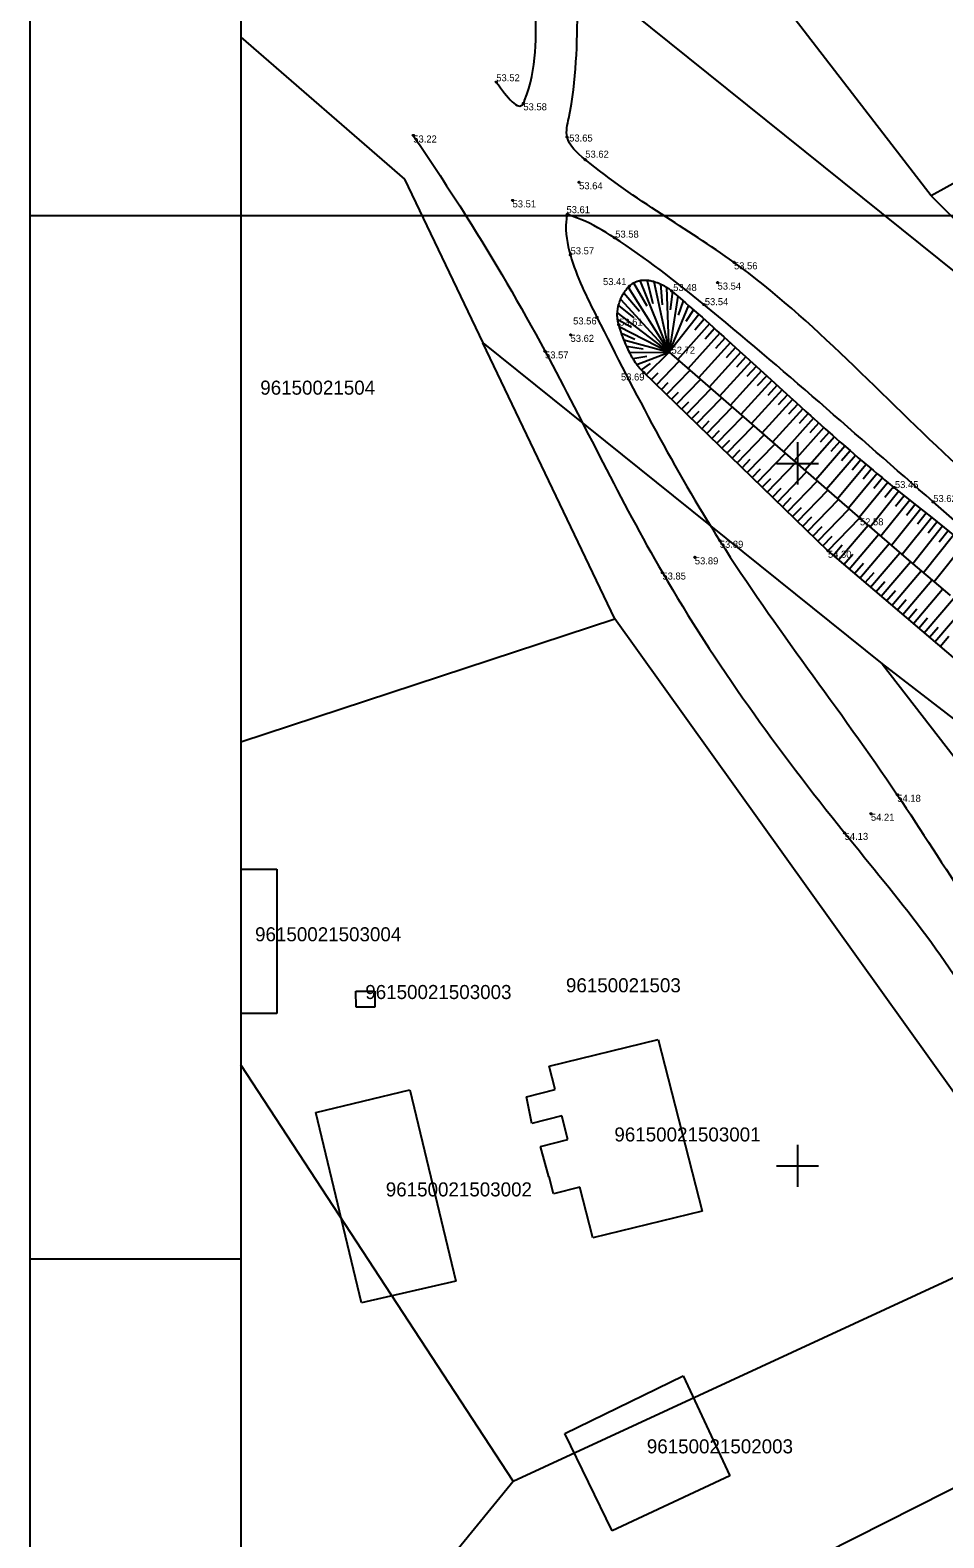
# Model space of a CAD drawing. Extents: x 578395 to 578590, y 418519 to 418816.
# Drawn here: x 578395.4 to 578460.4, y 418573.5 to 418680.8 of the extents above; entities that cross this region are included whole.
import ezdxf

# ---------------------------------------------------------------- set-up
doc = ezdxf.new("R2010")
doc.units = 0
for name, color, linetype in [('BUVE_EKAS_UZMR_####_#', 7, 'Continuous'), ('BUVE_EKAS_UZMR_TKST_#', 7, 'Continuous'), ('BUVE_EKAS_VEKT_####_#', 7, 'Continuous'), ('BUVE_EKAS_VEKT_TKST_#', 7, 'Continuous'), ('CELI_CMAL_####_####_#', 7, 'Continuous'), ('GEOD_ELEM_####_####_#', 7, 'Continuous'), ('RAMI_PLAN_####_TKST_#', 7, 'Continuous'), ('RELJ_AATZ_####_TKST_#', 7, 'Continuous'), ('RELJ_ELEM_####_####_#', 7, 'Continuous'), ('RELJ_NOGA_####_####_#', 7, 'Continuous'), ('RELJ_NOGL_####_####_#', 7, 'Continuous'), ('ROBZ_PROJ_####_####_#', 7, 'Continuous'), ('ROBZ_UZMR_####_####_#', 7, 'Continuous'), ('ROBZ_UZMR_####_TKST_#', 7, 'Continuous')]:
    doc.layers.add(name, color=color, linetype=linetype)

msp = doc.modelspace()

# ---------------------------------------------------------------- linework, layer by layer
at = {"layer": 'BUVE_EKAS_UZMR_####_#'}
for p, q in [((578432.32, 418607.09), (578440.09, 418608.98)), ((578440.09, 418608.98), (578443.22, 418596.77)), ((578432.74, 418605.42), (578432.32, 418607.09)), ((578415.69, 418603.8), (578422.39, 418605.4)), ((578422.39, 418605.4), (578425.68, 418591.78)), ((578430.69, 418604.9), (578432.74, 418605.42)), ((578431.09, 418603.02), (578430.69, 418604.9)), ((578418.96, 418590.25), (578415.69, 418603.8)), ((578433.21, 418603.56), (578431.09, 418603.02)), ((578433.64, 418601.87), (578433.21, 418603.56)), ((578431.71, 418601.38), (578433.64, 418601.87)), ((578432.29, 418599.22), (578431.71, 418601.38)), ((578432.31, 418599.22), (578432.29, 418599.22)), ((578432.62, 418598.01), (578432.31, 418599.22)), ((578434.5, 418598.48), (578432.62, 418598.01)), ((578435.42, 418594.87), (578434.5, 418598.48)), ((578443.22, 418596.77), (578435.42, 418594.87)), ((578425.68, 418591.78), (578418.96, 418590.25)), ((578433.42, 418580.94), (578441.86, 418585.05)), ((578441.86, 418585.05), (578445.19, 418577.93)), ((578436.8, 418574.01), (578433.42, 418580.94)), ((578449.67, 418571.29), (578468.65, 418580.87)), ((578445.19, 418577.93), (578436.8, 418574.01))]:
    msp.add_line(p, q, dxfattribs=at)
at = {"layer": 'BUVE_EKAS_VEKT_####_#'}
for p, q in [((578410.35, 418621.11), (578412.93, 418621.11)), ((578412.93, 418621.11), (578412.93, 418610.84)), ((578418.56, 418611.3), (578418.55, 418612.44)), ((578418.55, 418612.44), (578419.89, 418612.44)), ((578419.89, 418612.44), (578419.89, 418611.3)), ((578412.93, 418610.84), (578410.35, 418610.84)), ((578419.89, 418611.3), (578418.56, 418611.3))]:
    msp.add_line(p, q, dxfattribs=at)
at = {"layer": 'CELI_CMAL_####_####_#'}
for points in [[(578540.02, 418586.37), (578525.99, 418597.85), (578512.59, 418608.64), (578501.67, 418618.24), (578486.37, 418629.74), (578473.85, 418639.53), (578461.4, 418649.85), (578445.48, 418664.31), (578434.89, 418671.62), (578433.59, 418673.24), (578433.71, 418674.57), (578434.34, 418682.51), (578433.83, 418698.67), (578431.51, 418715.15), (578429.96, 418730.38), (578428.63, 418741.31), (578426.86, 418755.17), (578424.46, 418771.37), (578422.35, 418787.38), (578420.6, 418802.68)], [(578428.55, 418677.14), (578430.48, 418675.63), (578430.57, 418675.83), (578431.34, 418682.76), (578430.86, 418698.21), (578428.95, 418714.66), (578427.16, 418730.13), (578425.7, 418740.98), (578424.08, 418754.82), (578421.62, 418770.83), (578419.54, 418786.89), (578417.73, 418801.98)], [(578422.64, 418673.34), (578426.41, 418667.6), (578432.02, 418657.97), (578440.38, 418642.23), (578453.36, 418623.7), (578463.6, 418609.38), (578465.43, 418605.84), (578466.35, 418604.49)], [(578433.6, 418667.73), (578433.53, 418667.22), (578433.83, 418664.83), (578435.72, 418660.39), (578444.47, 418644.49), (578457.11, 418626.41), (578467.85, 418611.55), (578470.38, 418608.86), (578471.21, 418607.78)], [(578538.09, 418583.58), (578523.87, 418595.46), (578510.65, 418606.12), (578499.13, 418615.13), (578484.95, 418627.43), (578472.16, 418636.89), (578459.66, 418647.26), (578443.34, 418661.3), (578436.96, 418666.06), (578434.56, 418667.37), (578433.6, 418667.73)]]:
    msp.add_spline(points, degree=3, dxfattribs=at)
at = {"layer": 'GEOD_ELEM_####_####_#'}
for p, q in [((578450, 418651.5), (578450, 418650)), ((578448.5, 418650), (578450, 418650)), ((578450, 418650), (578450, 418648.5)), ((578450, 418650), (578451.5, 418650)), ((578450, 418601.5), (578450, 418600)), ((578448.5, 418600), (578450, 418600)), ((578450, 418600), (578450, 418598.5)), ((578450, 418600), (578451.5, 418600))]:
    msp.add_line(p, q, dxfattribs=at)
at = {"layer": 'RAMI_PLAN_####_TKST_#'}
for p, q in [((578395.35, 418667.61), (578395.35, 418816.11)), ((578395.35, 418519.11), (578395.35, 418667.61)), ((578590.35, 418667.61), (578395.35, 418667.61)), ((578410.35, 418593.36), (578395.35, 418593.36))]:
    msp.add_line(p, q, dxfattribs=at)
msp.add_lwpolyline([(578410.35, 418811.11), (578410.35, 418524.11), (578585.35, 418524.11), (578585.35, 418811.11)], close=True, dxfattribs=at)
at = {"layer": 'RELJ_ELEM_####_####_#'}
for centre in [(578428.55, 418677.14), (578430.48, 418675.63), (578422.64, 418673.34), (578433.59, 418673.24), (578434.89, 418671.62), (578434.45, 418670.01), (578429.71, 418668.72), (578433.6, 418667.73), (578436.96, 418666.06), (578433.83, 418664.83), (578445.48, 418664.31), (578438.02, 418662.61), (578441.05, 418662.27), (578444.31, 418662.87), (578443.34, 418661.3), (578435.72, 418660.39), (578437.27, 418659.87), (578433.84, 418659.15), (578432.02, 418657.97), (578440.85, 418657.91), (578439.06, 418656.46), (578456.87, 418648.29), (578459.66, 418647.26), (578454.45, 418646.09), (578444.47, 418644.49), (578452.17, 418643.78), (578442.69, 418643.31), (578440.38, 418642.23), (578457.11, 418626.41), (578455.23, 418625.06), (578453.36, 418623.7)]:
    msp.add_circle(centre, 0.05, dxfattribs=at)
at = {"layer": 'RELJ_NOGA_####_####_#'}
for p, q in [((578437.64, 418662.14), (578438.74, 418660.84)), ((578437.94, 418662.54), (578440.85, 418657.91)), ((578438.33, 418662.85), (578439.27, 418661.21)), ((578440.85, 418657.91), (578438.8, 418663.02)), ((578439.73, 418661.36), (578439.29, 418663.04)), ((578439.78, 418662.94), (578440.85, 418657.91)), ((578440.25, 418662.77), (578440.36, 418661.28)), ((578440.85, 418657.91), (578440.69, 418662.53)), ((578441.09, 418662.23), (578440.93, 418660.93)), ((578437.25, 418661.23), (578438.34, 418660.35)), ((578437.4, 418661.7), (578440.85, 418657.91)), ((578441.47, 418661.91), (578440.85, 418657.91)), ((578442.23, 418661.25), (578440.85, 418657.91)), ((578441.85, 418661.58), (578441.5, 418660.56)), ((578440.85, 418657.91), (578437.17, 418660.73)), ((578438.17, 418659.68), (578437.19, 418660.23)), ((578442.98, 418660.59), (578440.85, 418657.91)), ((578443.73, 418659.93), (578441.46, 418657.38)), ((578442.6, 418660.92), (578442.04, 418660.09)), ((578443.36, 418660.26), (578442.68, 418659.49)), ((578437.31, 418659.75), (578440.85, 418657.91)), ((578437.47, 418659.27), (578438.42, 418658.85)), ((578437.64, 418658.8), (578440.85, 418657.91)), ((578444.48, 418659.27), (578442.2, 418656.73)), ((578444.1, 418659.6), (578443.42, 418658.84)), ((578444.85, 418658.93), (578444.17, 418658.17)), ((578437.83, 418658.34), (578439.02, 418658.16)), ((578438.04, 418657.89), (578440.85, 418657.91)), ((578438.56, 418657.04), (578440.85, 418657.91)), ((578440.85, 418657.91), (578439.23, 418656.3)), ((578445.22, 418658.6), (578442.95, 418656.08)), ((578445.96, 418657.92), (578443.7, 418655.43)), ((578445.59, 418658.26), (578444.91, 418657.51)), ((578439.26, 418657.6), (578438.28, 418657.45)), ((578438.88, 418656.65), (578439.53, 418657.11)), ((578439.95, 418655.6), (578441.57, 418657.28)), ((578446.7, 418657.25), (578444.45, 418654.78)), ((578446.33, 418657.59), (578445.65, 418656.84)), ((578447.07, 418656.91), (578446.39, 418656.18)), ((578439.59, 418655.95), (578440.07, 418656.44)), ((578440.31, 418655.25), (578440.8, 418655.76)), ((578440.67, 418654.9), (578442.33, 418656.62)), ((578441.39, 418654.21), (578443.09, 418655.96)), ((578447.44, 418656.58), (578445.2, 418654.13)), ((578448.18, 418655.9), (578445.96, 418653.47)), ((578447.81, 418656.24), (578447.14, 418655.51)), ((578448.55, 418655.57), (578447.88, 418654.84)), ((578441.03, 418654.56), (578441.53, 418655.08)), ((578442.1, 418653.51), (578443.84, 418655.31)), ((578442.82, 418652.82), (578444.6, 418654.65)), ((578448.91, 418655.23), (578446.71, 418652.82)), ((578449.65, 418654.55), (578447.47, 418652.16)), ((578449.28, 418654.89), (578448.63, 418654.17)), ((578441.75, 418653.86), (578442.26, 418654.39)), ((578442.46, 418653.17), (578442.99, 418653.71)), ((578443.54, 418652.12), (578445.35, 418653.99)), ((578450.39, 418653.88), (578448.23, 418651.5)), ((578450.02, 418654.22), (578449.37, 418653.5)), ((578450.77, 418653.55), (578450.12, 418652.83)), ((578443.18, 418652.47), (578443.72, 418653.03)), ((578444.26, 418651.43), (578446.11, 418653.34)), ((578444.98, 418650.73), (578446.87, 418652.68)), ((578451.14, 418653.21), (578449, 418650.83)), ((578451.88, 418652.55), (578449.76, 418650.17)), ((578451.51, 418652.88), (578450.87, 418652.17)), ((578443.9, 418651.77), (578444.45, 418652.34)), ((578444.62, 418651.08), (578445.18, 418651.66)), ((578445.7, 418650.04), (578447.62, 418652.02)), ((578446.42, 418649.34), (578448.38, 418651.37)), ((578452.63, 418651.88), (578450.53, 418649.5)), ((578452.26, 418652.21), (578451.62, 418651.5)), ((578453.01, 418651.55), (578452.38, 418650.84)), ((578445.34, 418650.38), (578445.91, 418650.97)), ((578446.06, 418649.69), (578446.64, 418650.29)), ((578447.14, 418648.65), (578449.13, 418650.71)), ((578453.38, 418651.22), (578451.3, 418648.83)), ((578454.14, 418650.57), (578452.07, 418648.16)), ((578453.76, 418650.9), (578453.14, 418650.18)), ((578454.52, 418650.25), (578453.9, 418649.52)), ((578446.78, 418648.99), (578447.37, 418649.61)), ((578447.85, 418647.95), (578449.89, 418650.06)), ((578448.57, 418647.25), (578450.65, 418649.4)), ((578454.9, 418649.92), (578452.85, 418647.48)), ((578455.67, 418649.28), (578453.63, 418646.81)), ((578455.28, 418649.6), (578454.67, 418648.87)), ((578447.49, 418648.3), (578448.1, 418648.92)), ((578448.21, 418647.6), (578448.83, 418648.24)), ((578449.29, 418646.56), (578451.4, 418648.74)), ((578450.01, 418645.86), (578452.16, 418648.09)), ((578456.44, 418648.64), (578454.4, 418646.14)), ((578456.05, 418648.96), (578455.44, 418648.22)), ((578456.83, 418648.33), (578456.21, 418647.57)), ((578448.93, 418646.91), (578449.56, 418647.56)), ((578450.73, 418645.17), (578452.92, 418647.43)), ((578457.22, 418648.02), (578455.17, 418645.47)), ((578458, 418647.39), (578455.93, 418644.82)), ((578457.61, 418647.7), (578456.99, 418646.93)), ((578458.39, 418647.08), (578457.76, 418646.3)), ((578449.65, 418646.21), (578450.29, 418646.87)), ((578450.37, 418645.52), (578451.02, 418646.19)), ((578451.45, 418644.47), (578453.67, 418646.77)), ((578452.17, 418643.78), (578454.43, 418646.12)), ((578458.78, 418646.76), (578456.69, 418644.16)), ((578459.56, 418646.14), (578457.45, 418643.51)), ((578459.17, 418646.45), (578458.54, 418645.67)), ((578451.09, 418644.82), (578451.75, 418645.5)), ((578452.93, 418643.13), (578455.03, 418645.6)), ((578453.69, 418642.48), (578455.78, 418644.94)), ((578460.34, 418645.52), (578458.21, 418642.85)), ((578461.12, 418644.89), (578458.97, 418642.2)), ((578459.95, 418645.83), (578459.31, 418645.03)), ((578460.73, 418645.2), (578460.09, 418644.4)), ((578451.81, 418644.13), (578452.48, 418644.82)), ((578452.55, 418643.45), (578453.18, 418644.19)), ((578454.45, 418641.83), (578456.54, 418644.29)), ((578461.9, 418644.27), (578459.74, 418641.56)), ((578453.31, 418642.81), (578453.94, 418643.54)), ((578454.07, 418642.16), (578454.7, 418642.89)), ((578455.21, 418641.18), (578457.3, 418643.64)), ((578455.97, 418640.54), (578458.06, 418642.99)), ((578454.83, 418641.51), (578455.46, 418642.24)), ((578456.73, 418639.89), (578458.82, 418642.34)), ((578457.5, 418639.24), (578459.58, 418641.69)), ((578455.59, 418640.86), (578456.22, 418641.6)), ((578456.35, 418640.21), (578456.98, 418640.95)), ((578458.26, 418638.59), (578460.34, 418641.04)), ((578457.11, 418639.56), (578457.74, 418640.3)), ((578457.88, 418638.91), (578458.5, 418639.65)), ((578459.02, 418637.94), (578461.11, 418640.39)), ((578459.78, 418637.29), (578461.87, 418639.75)), ((578458.64, 418638.27), (578459.26, 418639)), ((578459.4, 418637.62), (578460.03, 418638.35)), ((578460.16, 418636.97), (578460.79, 418637.71))]:
    msp.add_line(p, q, dxfattribs=at)
for points in [[(578452.17, 418643.78), (578439.06, 418656.46), (578439.02, 418656.5), (578438.96, 418656.56), (578438.89, 418656.63), (578438.85, 418656.68), (578438.76, 418656.78), (578438.7, 418656.85), (578438.66, 418656.9), (578438.59, 418657), (578438.55, 418657.05), (578438.47, 418657.16), (578438.4, 418657.27), (578438.35, 418657.34), (578438.32, 418657.39), (578438.26, 418657.49), (578438.21, 418657.57), (578438.18, 418657.63), (578438.12, 418657.74), (578438.09, 418657.8), (578438.03, 418657.91), (578437.97, 418658.03), (578437.93, 418658.11), (578437.86, 418658.27), (578437.78, 418658.45), (578437.73, 418658.57), (578437.7, 418658.65), (578437.63, 418658.81), (578437.59, 418658.93), (578437.56, 418659.01), (578437.5, 418659.17), (578437.42, 418659.41), (578437.37, 418659.56), (578437.33, 418659.67), (578437.27, 418659.87), (578437.25, 418659.95), (578437.23, 418660.01), (578437.22, 418660.05), (578437.21, 418660.13), (578437.2, 418660.19), (578437.19, 418660.23), (578437.18, 418660.31), (578437.18, 418660.39), (578437.17, 418660.5), (578437.17, 418660.55), (578437.17, 418660.64), (578437.17, 418660.68), (578437.18, 418660.76), (578437.18, 418660.8), (578437.18, 418660.87), (578437.2, 418660.96), (578437.21, 418661.06), (578437.22, 418661.1), (578437.24, 418661.19), (578437.25, 418661.23), (578437.26, 418661.3), (578437.29, 418661.39), (578437.32, 418661.48), (578437.34, 418661.53), (578437.37, 418661.63), (578437.39, 418661.67), (578437.42, 418661.74), (578437.46, 418661.82), (578437.48, 418661.86), (578437.51, 418661.92), (578437.56, 418662.01), (578437.62, 418662.1), (578437.64, 418662.15), (578437.7, 418662.23), (578437.73, 418662.28), (578437.78, 418662.34), (578437.84, 418662.42), (578437.88, 418662.46), (578437.93, 418662.52), (578437.99, 418662.58), (578438.02, 418662.61), (578438.05, 418662.64), (578438.07, 418662.66), (578438.11, 418662.7), (578438.13, 418662.72), (578438.17, 418662.75), (578438.22, 418662.79), (578438.25, 418662.81), (578438.31, 418662.84), (578438.33, 418662.86), (578438.38, 418662.88), (578438.43, 418662.91), (578438.46, 418662.92), (578438.53, 418662.95), (578438.58, 418662.96), (578438.61, 418662.98), (578438.68, 418662.99), (578438.71, 418663), (578438.78, 418663.02), (578438.85, 418663.03), (578438.9, 418663.03), (578438.93, 418663.04), (578439, 418663.04), (578439.08, 418663.05), (578439.13, 418663.05), (578439.17, 418663.05), (578439.24, 418663.04), (578439.29, 418663.04), (578439.33, 418663.03), (578439.4, 418663.03), (578439.44, 418663.02), (578439.52, 418663.01), (578439.59, 418662.99), (578439.64, 418662.98), (578439.74, 418662.96), (578439.79, 418662.94), (578439.9, 418662.91), (578440.01, 418662.87), (578440.08, 418662.84), (578440.12, 418662.83), (578440.22, 418662.79), (578440.32, 418662.74), (578440.39, 418662.7), (578440.43, 418662.68), (578440.52, 418662.63), (578440.58, 418662.59), (578440.63, 418662.57), (578440.71, 418662.52), (578440.75, 418662.49), (578440.83, 418662.44), (578440.9, 418662.38), (578440.95, 418662.34), (578441.05, 418662.27), (578441.24, 418662.1), (578441.64, 418661.76), (578442.03, 418661.42), (578442.29, 418661.2), (578442.82, 418660.74), (578443.21, 418660.4), (578443.47, 418660.17), (578443.98, 418659.71), (578444.24, 418659.47), (578444.76, 418659.01), (578445.28, 418658.54), (578445.62, 418658.23), (578446.31, 418657.61), (578446.82, 418657.14), (578447.85, 418656.2), (578449.22, 418654.95), (578449.9, 418654.33), (578450.59, 418653.7), (578450.94, 418653.39), (578451.63, 418652.77), (578451.97, 418652.46), (578452.5, 418652), (578453.02, 418651.54), (578453.28, 418651.31), (578453.75, 418650.91), (578453.98, 418650.71), (578454.33, 418650.4), (578454.86, 418649.95), (578455.39, 418649.51), (578455.66, 418649.28), (578456.02, 418648.99), (578456.2, 418648.84), (578456.47, 418648.62), (578456.87, 418648.29), (578458.48, 418647), (578459.56, 418646.14), (578461.71, 418644.42)], [(578452.17, 418643.78), (578466.19, 418631.83)]]:
    msp.add_lwpolyline(points, dxfattribs=at)
at = {"layer": 'RELJ_NOGL_####_####_#'}
msp.add_lwpolyline([(578440.85, 418657.91), (578454.45, 418646.09), (578454.97, 418645.65), (578456.01, 418644.75), (578457.05, 418643.85), (578457.74, 418643.26), (578458.21, 418642.86), (578459.13, 418642.07), (578460.18, 418641.18), (578460.88, 418640.59)], dxfattribs=at)
at = {"layer": 'ROBZ_PROJ_####_####_#'}
msp.add_line((578456.04, 418635.73), (578533.75, 418575.71), dxfattribs=at)
at = {"layer": 'ROBZ_UZMR_####_####_#'}
for p, q in [((578459.53, 418669.04), (578440.17, 418694.13)), ((578479.13, 418649.24), (578426.39, 418691.61)), ((578410.35, 418680.35), (578422.02, 418670.23)), ((578470.44, 418675.1), (578459.53, 418669.04)), ((578422.02, 418670.23), (578427.6, 418658.57)), ((578459.53, 418669.04), (578479.13, 418649.24)), ((578427.6, 418658.57), (578456.04, 418635.73)), ((578437, 418638.94), (578427.6, 418658.57)), ((578410.35, 418630.17), (578437, 418638.94)), ((578468.2, 418595.33), (578437, 418638.94)), ((578456.04, 418635.73), (578469.51, 418618.29)), ((578429.74, 418577.54), (578410.35, 418607.18)), ((578429.74, 418577.54), (578468.2, 418595.33)), ((578412.77, 418556.81), (578429.74, 418577.54))]:
    msp.add_line(p, q, dxfattribs=at)

# ---------------------------------------------------------------- texts
at = {"layer": 'BUVE_EKAS_UZMR_TKST_#'}
for s, p in [('96150021503001', (578436.96, 418601.73)), ('96150021503002', (578420.68, 418597.82)), ('96150021502003', (578439.27, 418579.53))]:
    msp.add_text(s, height=1, dxfattribs=at).set_placement(p)
at = {"layer": 'BUVE_EKAS_VEKT_TKST_#'}
for s, p in [('96150021503004', (578411.37, 418615.98)), ('96150021503003', (578419.22, 418611.87))]:
    msp.add_text(s, height=1, dxfattribs=at).set_placement(p)
at = {"layer": 'RELJ_AATZ_####_TKST_#'}
for s, p in [('53.52', (578428.55, 418677.2)), ('53.58', (578430.48, 418675.13)), ('53.22', (578422.64, 418672.84)), ('53.65', (578433.74, 418672.91)), ('53.62', (578434.89, 418671.76)), ('53.64', (578434.45, 418669.51)), ('53.51', (578429.71, 418668.22)), ('53.61', (578433.55, 418667.81)), ('53.58', (578437.02, 418666.07)), ('53.57', (578433.84, 418664.88)), ('53.56', (578445.48, 418663.81)), ('53.41', (578436.15, 418662.69)), ('53.48', (578441.15, 418662.27)), ('53.54', (578444.31, 418662.37)), ('53.54', (578443.4, 418661.26)), ('53.56', (578434.02, 418659.89)), ('53.61', (578437.3, 418659.8)), ('53.62', (578433.84, 418658.65)), ('53.57', (578432.02, 418657.47)), ('52.72', (578441.03, 418657.81)), ('53.69', (578437.43, 418655.9)), ('53.45', (578456.94, 418648.24)), ('53.62', (578459.67, 418647.25)), ('52.58', (578454.45, 418645.59)), ('53.89', (578444.47, 418643.99)), ('54.30', (578452.17, 418643.28)), ('53.89', (578442.69, 418642.81)), ('53.85', (578440.38, 418641.73)), ('54.18', (578457.11, 418625.91)), ('54.21', (578455.23, 418624.56)), ('54.13', (578453.36, 418623.2))]:
    msp.add_text(s, height=0.5, dxfattribs=at).set_placement(p)
at = {"layer": 'ROBZ_UZMR_####_TKST_#'}
for s, p in [('96150021504', (578411.74, 418654.89)), ('96150021503', (578433.51, 418612.35))]:
    msp.add_text(s, height=1, dxfattribs=at).set_placement(p)

doc.saveas('drawing.dxf')
